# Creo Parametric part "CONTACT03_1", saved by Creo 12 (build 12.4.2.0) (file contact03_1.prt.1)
Units: Custom; MM, KILOGRAM, SECS

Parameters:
  PTC_WM_ITERATION = "0"
  PTC_WM_VERSION = "-.0"
  PTC_WM_LIFECYCLE_STATE = "In Work"
  PTC_WM_LIFECYCLE = "MO_CADDocument"
  PTC_WM_CREATED_BY = "Maximilian Roepper (Z0017RMS: MO)"
  PTC_WM_CREATED_ON = "18-Sep-26 11:36:42 AM"
  PTC_WM_MODIFIED_BY = "Maximilian Roepper (Z0017RMS: MO)"
  PTC_WM_MODIFIED_ON = "18-Sep-26 11:36:46 AM"
  PDMLINKNUMBER = "PDM000071454975"
  PTC_WM_NAME = "contact03_1.prt"
  PTC_WM_NUMBER = "PDM000071454975"

Other parameters: WEIGHT, WEIGHT_FACTOR, WEIGHT_ADD, _MASS_TEMP, _DIFF_TEMP, MC_ERRORS, SUPPLIER

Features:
  1. coordinate system
  2. datum plane "PRT_YZ"
  3. datum plane "PRT_XY"
  4. datum plane "PRT_XZ"
  5. coordinate system
  6. datum axis
  7. datum axis
  8. datum axis
  9. coordinate system
  10. imported feature

Other named items: PRT, SIEMENS_MO, DRW_VIEW_ORG, PRT_X, PRT_Y, PRT_Z, CS0, ROUGH_GROB

Layers: 00_STD_CSYS-KSYS, 01_STD_PLANES-EBENEN, 02_STD_AXES-ACHSEN, 03_STD_CSYS-KSYS, 24_IMPORT_FEAT-IMPORT_KE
